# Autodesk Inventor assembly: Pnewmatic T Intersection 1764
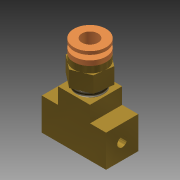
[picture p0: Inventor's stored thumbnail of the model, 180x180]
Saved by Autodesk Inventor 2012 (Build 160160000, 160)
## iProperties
Created: 2010-02
Part Number: Pnewmatic T Intersection 1764
Document SubType Name: Assembly
Designer: jgehrig
Author: jgehrig
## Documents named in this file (3)
- R:\CAD Archives\Pneumatics_1764\Pneumatics_T_Intersection_1764\Pneumatic_T_Intersection_1764.iam
- R:\CAD Archives\Pneumatics_1764\Pneumatics_T_Intersection_1764\Pneumatics_T_Intersection_1764.ipt
- R:\CAD Archives\Pneumatics_1764\Pneumatics_T_Intersection_1764\Pnewmatic_Screw_1764\Pneumatic_Screw_1764.iam
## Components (2 placed, 2 different names)
1. Pneumatics_T_Intersection_1764:1 — Mate:1, Mate:2
2. Pneumatic_Screw_1764:1 [sub-assembly] — Mate:1, Mate:2
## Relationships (2: Mate 2)
- Mate:1: Pneumatics_T_Intersection_1764:1 ↔ Pneumatic_Screw_1764:1
- Mate:2: Pneumatics_T_Intersection_1764:1 ↔ Pneumatic_Screw_1764:1
